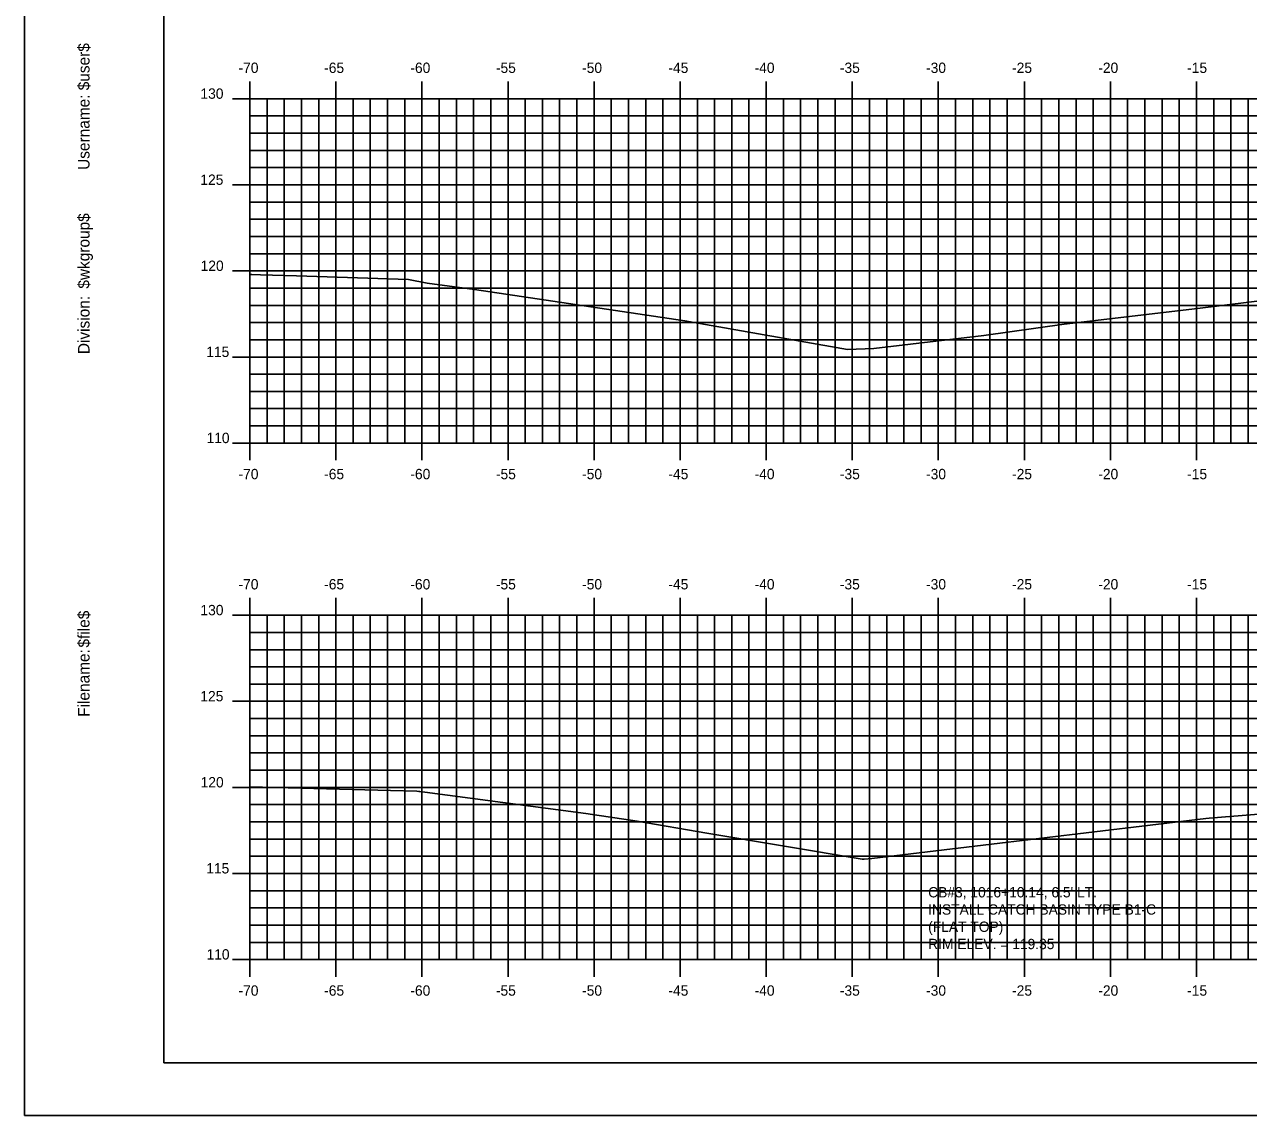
# Model space of a CAD drawing. Extents: x 853291 to 853462, y 365624 to 365734.
# Drawn here: x 853290.7 to 853361.8, y 365624 to 365687.3 of the extents above; entities that cross this region are included whole.
import ezdxf

# ---------------------------------------------------------------- set-up
doc = ezdxf.new("R2010")
doc.units = 0
for name, color, linetype in [('BORDER', 7, 'Continuous'), ('D_Drainage_Text', 7, 'Continuous'), ('H_V ANNOTATION', 7, 'Continuous'), ('MAJOR', 7, 'Continuous'), ('MINOR', 7, 'Continuous'), ('PLOT BOUNDARY', 7, 'Continuous'), ('S_Roadway_Centerline', 7, 'Continuous')]:
    doc.layers.add(name, color=color, linetype=linetype)

msp = doc.modelspace()

# ---------------------------------------------------------------- linework, layer by layer
at = {"layer": 'BORDER'}
msp.add_lwpolyline([(853298.818, 365627.027), (853458.818, 365627.027), (853458.818, 365732.027), (853298.818, 365732.027)], close=True, dxfattribs=at)
at = {"layer": 'MAJOR'}
for p, q in [((853303.818, 365684.029), (853303.818, 365683.027)), ((853308.818, 365684.029), (853308.818, 365683.027)), ((853313.818, 365684.029), (853313.818, 365683.027)), ((853318.818, 365684.029), (853318.818, 365683.027)), ((853323.818, 365684.029), (853323.818, 365683.027)), ((853328.818, 365684.029), (853328.818, 365683.027)), ((853333.818, 365684.029), (853333.818, 365683.027)), ((853338.818, 365684.029), (853338.818, 365683.027)), ((853343.818, 365684.029), (853343.818, 365683.027)), ((853348.818, 365684.029), (853348.818, 365683.027)), ((853353.818, 365684.029), (853353.818, 365683.027)), ((853358.818, 365684.029), (853358.818, 365683.027)), ((853302.816, 365683.027), (853303.818, 365683.027)), ((853303.818, 365683.027), (853443.818, 365683.027)), ((853303.818, 365663.027), (853303.818, 365683.027)), ((853303.818, 365663.027), (853303.818, 365683.027)), ((853303.818, 365683.027), (853443.818, 365683.027)), ((853308.818, 365663.027), (853308.818, 365683.027)), ((853313.818, 365663.027), (853313.818, 365683.027)), ((853318.818, 365663.027), (853318.818, 365683.027)), ((853323.818, 365663.027), (853323.818, 365683.027)), ((853328.818, 365663.027), (853328.818, 365683.027)), ((853333.818, 365663.027), (853333.818, 365683.027)), ((853338.818, 365663.027), (853338.818, 365683.027)), ((853343.818, 365663.027), (853343.818, 365683.027)), ((853348.818, 365663.027), (853348.818, 365683.027)), ((853353.818, 365663.027), (853353.818, 365683.027)), ((853358.818, 365663.027), (853358.818, 365683.027)), ((853302.816, 365678.027), (853303.818, 365678.027)), ((853303.818, 365678.027), (853443.818, 365678.027)), ((853302.816, 365673.027), (853303.818, 365673.027)), ((853303.818, 365673.027), (853443.818, 365673.027)), ((853302.816, 365668.027), (853303.818, 365668.027)), ((853303.818, 365668.027), (853443.818, 365668.027)), ((853302.816, 365663.027), (853303.818, 365663.027)), ((853303.818, 365663.027), (853443.818, 365663.027)), ((853303.818, 365663.027), (853443.818, 365663.027)), ((853303.818, 365662.025), (853303.818, 365663.027)), ((853308.818, 365662.025), (853308.818, 365663.027)), ((853313.818, 365662.025), (853313.818, 365663.027)), ((853318.818, 365662.025), (853318.818, 365663.027)), ((853323.818, 365662.025), (853323.818, 365663.027)), ((853328.818, 365662.025), (853328.818, 365663.027)), ((853333.818, 365662.025), (853333.818, 365663.027)), ((853338.818, 365662.025), (853338.818, 365663.027)), ((853343.818, 365662.025), (853343.818, 365663.027)), ((853348.818, 365662.025), (853348.818, 365663.027)), ((853353.818, 365662.025), (853353.818, 365663.027)), ((853358.818, 365662.025), (853358.818, 365663.027)), ((853303.818, 365654.029), (853303.818, 365653.027)), ((853308.818, 365654.029), (853308.818, 365653.027)), ((853313.818, 365654.029), (853313.818, 365653.027)), ((853318.818, 365654.029), (853318.818, 365653.027)), ((853323.818, 365654.029), (853323.818, 365653.027)), ((853328.818, 365654.029), (853328.818, 365653.027)), ((853333.818, 365654.029), (853333.818, 365653.027)), ((853338.818, 365654.029), (853338.818, 365653.027)), ((853343.818, 365654.029), (853343.818, 365653.027)), ((853348.818, 365654.029), (853348.818, 365653.027)), ((853353.818, 365654.029), (853353.818, 365653.027)), ((853358.818, 365654.029), (853358.818, 365653.027)), ((853302.816, 365653.027), (853303.818, 365653.027)), ((853303.818, 365653.027), (853443.818, 365653.027)), ((853303.818, 365633.027), (853303.818, 365653.027)), ((853303.818, 365633.027), (853303.818, 365653.027)), ((853303.818, 365653.027), (853443.818, 365653.027)), ((853308.818, 365633.027), (853308.818, 365653.027)), ((853313.818, 365633.027), (853313.818, 365653.027)), ((853318.818, 365633.027), (853318.818, 365653.027)), ((853323.818, 365633.027), (853323.818, 365653.027)), ((853328.818, 365633.027), (853328.818, 365653.027)), ((853333.818, 365633.027), (853333.818, 365653.027)), ((853338.818, 365633.027), (853338.818, 365653.027)), ((853343.818, 365633.027), (853343.818, 365653.027)), ((853348.818, 365633.027), (853348.818, 365653.027)), ((853353.818, 365633.027), (853353.818, 365653.027)), ((853358.818, 365633.027), (853358.818, 365653.027)), ((853302.816, 365648.027), (853303.818, 365648.027)), ((853303.818, 365648.027), (853443.818, 365648.027)), ((853302.816, 365643.027), (853303.818, 365643.027)), ((853303.818, 365643.027), (853443.818, 365643.027)), ((853302.816, 365638.027), (853303.818, 365638.027)), ((853303.818, 365638.027), (853443.818, 365638.027)), ((853302.816, 365633.027), (853303.818, 365633.027)), ((853303.818, 365633.027), (853443.818, 365633.027)), ((853303.818, 365633.027), (853443.818, 365633.027)), ((853303.818, 365632.025), (853303.818, 365633.027)), ((853308.818, 365632.025), (853308.818, 365633.027)), ((853313.818, 365632.025), (853313.818, 365633.027)), ((853318.818, 365632.025), (853318.818, 365633.027)), ((853323.818, 365632.025), (853323.818, 365633.027)), ((853328.818, 365632.025), (853328.818, 365633.027)), ((853333.818, 365632.025), (853333.818, 365633.027)), ((853338.818, 365632.025), (853338.818, 365633.027)), ((853343.818, 365632.025), (853343.818, 365633.027)), ((853348.818, 365632.025), (853348.818, 365633.027)), ((853353.818, 365632.025), (853353.818, 365633.027)), ((853358.818, 365632.025), (853358.818, 365633.027))]:
    msp.add_line(p, q, dxfattribs=at)
at = {"layer": 'MINOR'}
for p, q in [((853304.818, 365663.027), (853304.818, 365683.027)), ((853305.818, 365663.027), (853305.818, 365683.027)), ((853306.818, 365663.027), (853306.818, 365683.027)), ((853307.818, 365663.027), (853307.818, 365683.027)), ((853309.818, 365663.027), (853309.818, 365683.027)), ((853310.818, 365663.027), (853310.818, 365683.027)), ((853311.818, 365663.027), (853311.818, 365683.027)), ((853312.818, 365663.027), (853312.818, 365683.027)), ((853314.818, 365663.027), (853314.818, 365683.027)), ((853315.818, 365663.027), (853315.818, 365683.027)), ((853316.818, 365663.027), (853316.818, 365683.027)), ((853317.818, 365663.027), (853317.818, 365683.027)), ((853319.818, 365663.027), (853319.818, 365683.027)), ((853320.818, 365663.027), (853320.818, 365683.027)), ((853321.818, 365663.027), (853321.818, 365683.027)), ((853322.818, 365663.027), (853322.818, 365683.027)), ((853324.818, 365663.027), (853324.818, 365683.027)), ((853325.818, 365663.027), (853325.818, 365683.027)), ((853326.818, 365663.027), (853326.818, 365683.027)), ((853327.818, 365663.027), (853327.818, 365683.027)), ((853329.818, 365663.027), (853329.818, 365683.027)), ((853330.818, 365663.027), (853330.818, 365683.027)), ((853331.818, 365663.027), (853331.818, 365683.027)), ((853332.818, 365663.027), (853332.818, 365683.027)), ((853334.818, 365663.027), (853334.818, 365683.027)), ((853335.818, 365663.027), (853335.818, 365683.027)), ((853336.818, 365663.027), (853336.818, 365683.027)), ((853337.818, 365663.027), (853337.818, 365683.027)), ((853339.818, 365663.027), (853339.818, 365683.027)), ((853340.818, 365663.027), (853340.818, 365683.027)), ((853341.818, 365663.027), (853341.818, 365683.027)), ((853342.818, 365663.027), (853342.818, 365683.027)), ((853344.818, 365663.027), (853344.818, 365683.027)), ((853345.818, 365663.027), (853345.818, 365683.027)), ((853346.818, 365663.027), (853346.818, 365683.027)), ((853347.818, 365663.027), (853347.818, 365683.027)), ((853349.818, 365663.027), (853349.818, 365683.027)), ((853350.818, 365663.027), (853350.818, 365683.027)), ((853351.818, 365663.027), (853351.818, 365683.027)), ((853352.818, 365663.027), (853352.818, 365683.027)), ((853354.818, 365663.027), (853354.818, 365683.027)), ((853355.818, 365663.027), (853355.818, 365683.027)), ((853356.818, 365663.027), (853356.818, 365683.027)), ((853357.818, 365663.027), (853357.818, 365683.027)), ((853359.818, 365663.027), (853359.818, 365683.027)), ((853360.818, 365663.027), (853360.818, 365683.027)), ((853361.818, 365663.027), (853361.818, 365683.027)), ((853303.818, 365682.027), (853443.818, 365682.027)), ((853303.818, 365682.027), (853304.82, 365682.027)), ((853303.818, 365681.027), (853443.818, 365681.027)), ((853303.818, 365681.027), (853304.82, 365681.027)), ((853303.818, 365680.027), (853443.818, 365680.027)), ((853303.818, 365680.027), (853304.82, 365680.027)), ((853303.818, 365679.027), (853443.818, 365679.027)), ((853303.818, 365679.027), (853304.82, 365679.027)), ((853303.818, 365677.027), (853443.818, 365677.027)), ((853303.818, 365677.027), (853304.82, 365677.027)), ((853303.818, 365676.027), (853443.818, 365676.027)), ((853303.818, 365676.027), (853304.82, 365676.027)), ((853303.818, 365675.027), (853443.818, 365675.027)), ((853303.818, 365675.027), (853304.82, 365675.027)), ((853303.818, 365674.027), (853443.818, 365674.027)), ((853303.818, 365674.027), (853304.82, 365674.027)), ((853303.818, 365672.027), (853443.818, 365672.027)), ((853303.818, 365672.027), (853304.82, 365672.027)), ((853303.818, 365671.027), (853443.818, 365671.027)), ((853303.818, 365671.027), (853304.82, 365671.027)), ((853303.818, 365670.027), (853443.818, 365670.027)), ((853303.818, 365670.027), (853304.82, 365670.027)), ((853303.818, 365669.027), (853443.818, 365669.027)), ((853303.818, 365669.027), (853304.82, 365669.027)), ((853303.818, 365667.027), (853443.818, 365667.027)), ((853303.818, 365667.027), (853304.82, 365667.027)), ((853303.818, 365666.027), (853443.818, 365666.027)), ((853303.818, 365666.027), (853304.82, 365666.027)), ((853303.818, 365665.027), (853443.818, 365665.027)), ((853303.818, 365665.027), (853304.82, 365665.027)), ((853303.818, 365664.027), (853443.818, 365664.027)), ((853303.818, 365664.027), (853304.82, 365664.027)), ((853303.818, 365633.027), (853303.818, 365653.027)), ((853304.818, 365633.027), (853304.818, 365653.027)), ((853305.818, 365633.027), (853305.818, 365653.027)), ((853306.818, 365633.027), (853306.818, 365653.027)), ((853307.818, 365633.027), (853307.818, 365653.027)), ((853309.818, 365633.027), (853309.818, 365653.027)), ((853310.818, 365633.027), (853310.818, 365653.027)), ((853311.818, 365633.027), (853311.818, 365653.027)), ((853312.818, 365633.027), (853312.818, 365653.027)), ((853314.818, 365633.027), (853314.818, 365653.027)), ((853315.818, 365633.027), (853315.818, 365653.027)), ((853316.818, 365633.027), (853316.818, 365653.027)), ((853317.818, 365633.027), (853317.818, 365653.027)), ((853319.818, 365633.027), (853319.818, 365653.027)), ((853320.818, 365633.027), (853320.818, 365653.027)), ((853321.818, 365633.027), (853321.818, 365653.027)), ((853322.818, 365633.027), (853322.818, 365653.027)), ((853324.818, 365633.027), (853324.818, 365653.027)), ((853325.818, 365633.027), (853325.818, 365653.027)), ((853326.818, 365633.027), (853326.818, 365653.027)), ((853327.818, 365633.027), (853327.818, 365653.027)), ((853329.818, 365633.027), (853329.818, 365653.027)), ((853330.818, 365633.027), (853330.818, 365653.027)), ((853331.818, 365633.027), (853331.818, 365653.027)), ((853332.818, 365633.027), (853332.818, 365653.027)), ((853334.818, 365633.027), (853334.818, 365653.027)), ((853335.818, 365633.027), (853335.818, 365653.027)), ((853336.818, 365633.027), (853336.818, 365653.027)), ((853337.818, 365633.027), (853337.818, 365653.027)), ((853339.818, 365633.027), (853339.818, 365653.027)), ((853340.818, 365633.027), (853340.818, 365653.027)), ((853341.818, 365633.027), (853341.818, 365653.027)), ((853342.818, 365633.027), (853342.818, 365653.027)), ((853344.818, 365633.027), (853344.818, 365653.027)), ((853345.818, 365633.027), (853345.818, 365653.027)), ((853346.818, 365633.027), (853346.818, 365653.027)), ((853347.818, 365633.027), (853347.818, 365653.027)), ((853349.818, 365633.027), (853349.818, 365653.027)), ((853350.818, 365633.027), (853350.818, 365653.027)), ((853351.818, 365633.027), (853351.818, 365653.027)), ((853352.818, 365633.027), (853352.818, 365653.027)), ((853354.818, 365633.027), (853354.818, 365653.027)), ((853355.818, 365633.027), (853355.818, 365653.027)), ((853356.818, 365633.027), (853356.818, 365653.027)), ((853357.818, 365633.027), (853357.818, 365653.027)), ((853359.818, 365633.027), (853359.818, 365653.027)), ((853360.818, 365633.027), (853360.818, 365653.027)), ((853361.818, 365633.027), (853361.818, 365653.027)), ((853303.818, 365652.027), (853443.818, 365652.027)), ((853303.818, 365652.027), (853304.82, 365652.027)), ((853303.818, 365651.027), (853443.818, 365651.027)), ((853303.818, 365651.027), (853304.82, 365651.027)), ((853303.818, 365650.027), (853443.818, 365650.027)), ((853303.818, 365650.027), (853304.82, 365650.027)), ((853303.818, 365649.027), (853443.818, 365649.027)), ((853303.818, 365649.027), (853304.82, 365649.027)), ((853303.818, 365647.027), (853443.818, 365647.027)), ((853303.818, 365647.027), (853304.82, 365647.027)), ((853303.818, 365646.027), (853443.818, 365646.027)), ((853303.818, 365646.027), (853304.82, 365646.027)), ((853303.818, 365645.027), (853443.818, 365645.027)), ((853303.818, 365645.027), (853304.82, 365645.027)), ((853303.818, 365644.027), (853443.818, 365644.027)), ((853303.818, 365644.027), (853304.82, 365644.027)), ((853303.818, 365642.027), (853443.818, 365642.027)), ((853303.818, 365642.027), (853304.82, 365642.027)), ((853303.818, 365641.027), (853443.818, 365641.027)), ((853303.818, 365641.027), (853304.82, 365641.027)), ((853303.818, 365640.027), (853443.818, 365640.027)), ((853303.818, 365640.027), (853304.82, 365640.027)), ((853303.818, 365639.027), (853443.818, 365639.027)), ((853303.818, 365639.027), (853304.82, 365639.027)), ((853303.818, 365637.027), (853443.818, 365637.027)), ((853303.818, 365637.027), (853304.82, 365637.027)), ((853303.818, 365636.027), (853443.818, 365636.027)), ((853303.818, 365636.027), (853304.82, 365636.027)), ((853303.818, 365635.027), (853443.818, 365635.027)), ((853303.818, 365635.027), (853304.82, 365635.027)), ((853303.818, 365634.027), (853443.818, 365634.027)), ((853303.818, 365634.027), (853304.82, 365634.027))]:
    msp.add_line(p, q, dxfattribs=at)
at = {"layer": 'PLOT BOUNDARY'}
msp.add_lwpolyline([(853290.725, 365623.968), (853460.725, 365623.968), (853460.725, 365733.968), (853290.725, 365733.968)], close=True, dxfattribs=at)
at = {"layer": 'S_Roadway_Centerline'}
for points in [[(853303.818, 365672.819), (853303.943, 365672.816), (853304.446, 365672.795), (853306.538, 365672.742), (853313.041, 365672.525), (853314.119, 365672.323), (853316.862, 365671.939), (853329.095, 365670.125), (853329.641, 365670.036), (853338.542, 365668.471), (853340.066, 365668.513), (853346.453, 365669.28), (853351.131, 365669.943), (853358.875, 365670.837), (853363.418, 365671.415)], [(853303.818, 365643.052), (853311.989, 365642.839), (853313.521, 365642.802), (853313.633, 365642.798), (853313.685, 365642.791), (853323.334, 365641.506), (853326.319, 365641.074), (853330.372, 365640.366), (853339.395, 365638.864), (853339.511, 365638.855), (853339.963, 365638.906), (853359.353, 365641.222), (853359.562, 365641.24), (853378.698, 365642.784)]]:
    msp.add_lwpolyline(points, dxfattribs=at)

# ---------------------------------------------------------------- texts
at = {"layer": 'BORDER'}
for s, p in [('$user$', (853294.503, 365683.518)), ('Username:', (853294.503, 365678.895)), ('$wkgroup$', (853294.503, 365671.996)), ('Division:', (853294.503, 365668.193)), ('$file$', (853294.503, 365651.152)), ('Filename:', (853294.503, 365647.125))]:
    msp.add_text(s, height=0.6696, rotation=90, dxfattribs=at).set_placement(p)
at = {"layer": 'D_Drainage_Text'}
for s, p in [("CB#3, 1016+10.14, 6.5' LT. ", (853343.227, 365636.637)), ('INSTALL CATCH BASIN TYPE B1-C', (853343.227, 365635.635)), ('(FLAT TOP) ', (853343.227, 365634.633)), ('RIM ELEV. = 119.35', (853343.227, 365633.631))]:
    msp.add_text(s, height=0.6, dxfattribs=at).set_placement(p)
at = {"layer": 'H_V ANNOTATION'}
for s, p in [('-70', (853303.16, 365684.527)), ('-65', (853308.136, 365684.527)), ('-60', (853313.144, 365684.527)), ('-55', (853318.114, 365684.527)), ('-50', (853323.122, 365684.527)), ('-45', (853328.136, 365684.527)), ('-40', (853333.144, 365684.527)), ('-35', (853338.098, 365684.527)), ('-30', (853343.106, 365684.527)), ('-25', (853348.104, 365684.527)), ('-20', (853353.112, 365684.527)), ('-15', (853358.275, 365684.527)), ('130', (853300.948, 365683.027)), ('125', (853300.943, 365678.027)), ('120', (853300.959, 365673.027)), ('115', (853301.285, 365668.027)), ('110', (853301.301, 365663.027)), ('-70', (853303.16, 365660.927)), ('-65', (853308.136, 365660.927)), ('-60', (853313.144, 365660.927)), ('-55', (853318.114, 365660.927)), ('-50', (853323.122, 365660.927)), ('-45', (853328.136, 365660.927)), ('-40', (853333.144, 365660.927)), ('-35', (853338.098, 365660.927)), ('-30', (853343.106, 365660.927)), ('-25', (853348.104, 365660.927)), ('-20', (853353.112, 365660.927)), ('-15', (853358.275, 365660.927)), ('-70', (853303.16, 365654.527)), ('-65', (853308.136, 365654.527)), ('-60', (853313.144, 365654.527)), ('-55', (853318.114, 365654.527)), ('-50', (853323.122, 365654.527)), ('-45', (853328.136, 365654.527)), ('-40', (853333.144, 365654.527)), ('-35', (853338.098, 365654.527)), ('-30', (853343.106, 365654.527)), ('-25', (853348.104, 365654.527)), ('-20', (853353.112, 365654.527)), ('-15', (853358.275, 365654.527)), ('130', (853300.948, 365653.027)), ('125', (853300.943, 365648.027)), ('120', (853300.959, 365643.027)), ('115', (853301.285, 365638.027)), ('110', (853301.301, 365633.027)), ('-70', (853303.16, 365630.927)), ('-65', (853308.136, 365630.927)), ('-60', (853313.144, 365630.927)), ('-55', (853318.114, 365630.927)), ('-50', (853323.122, 365630.927)), ('-45', (853328.136, 365630.927)), ('-40', (853333.144, 365630.927)), ('-35', (853338.098, 365630.927)), ('-30', (853343.106, 365630.927)), ('-25', (853348.104, 365630.927)), ('-20', (853353.112, 365630.927)), ('-15', (853358.275, 365630.927))]:
    msp.add_text(s, height=0.6, dxfattribs=at).set_placement(p)
at = {"layer": 'MAJOR'}
for p in [(853303.814, 365663.027), (853303.814, 365633.027)]:
    msp.add_text('-', height=0.006, dxfattribs=at).set_placement(p)

doc.saveas('drawing.dxf')
